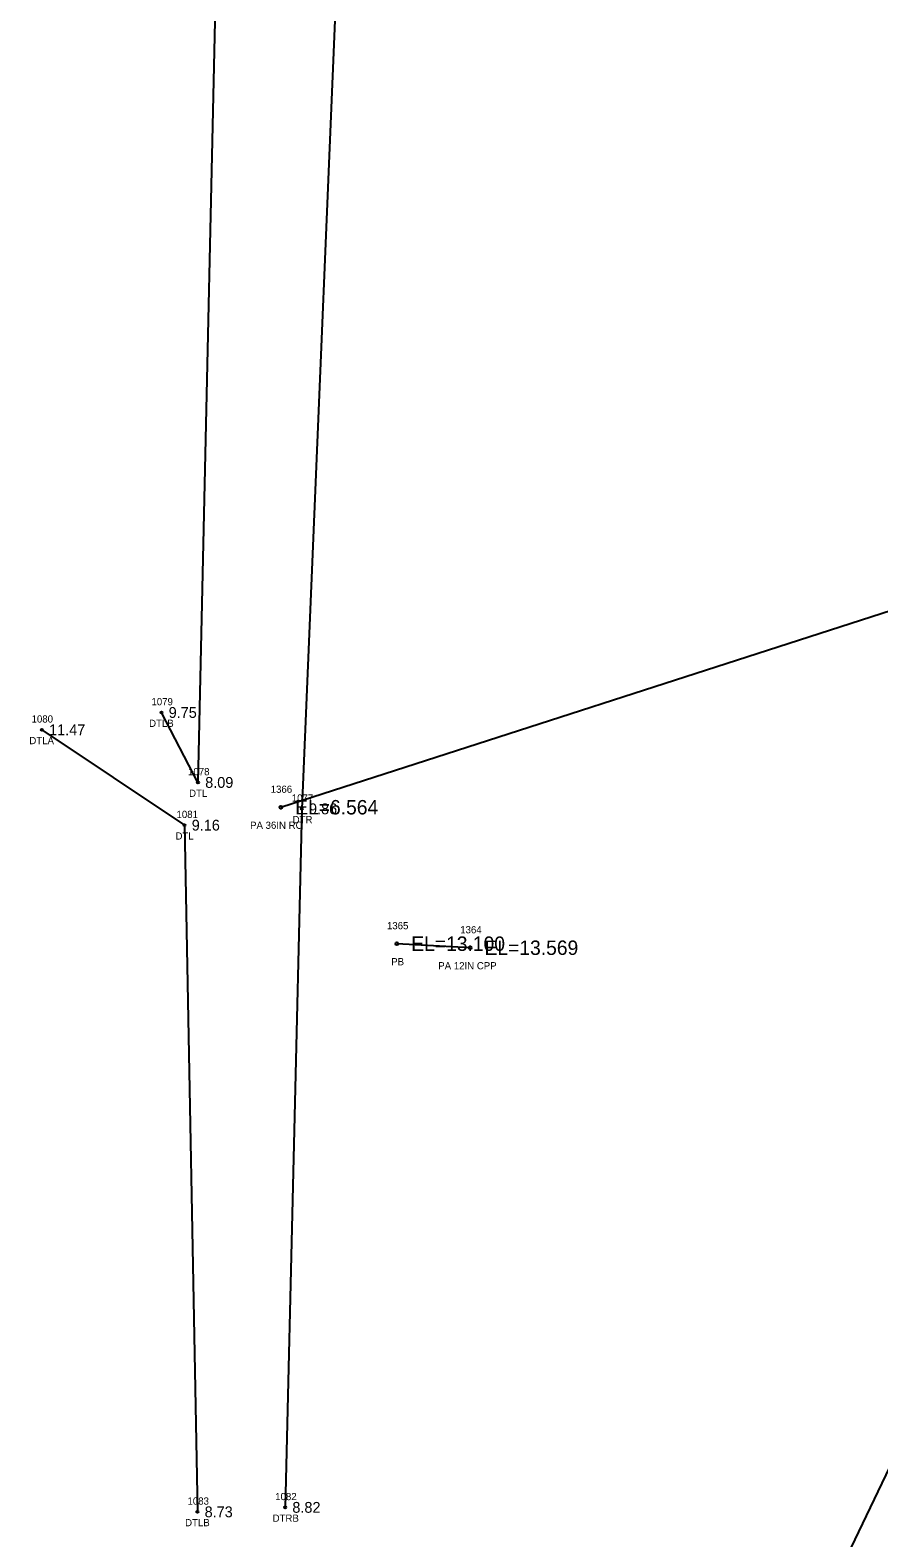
# Model space of a CAD drawing. Extents: x 2072307 to 2072993, y 127574 to 129736.
# Drawn here: x 2072379 to 2072496.8, y 129052.1 to 129261.4 of the extents above; entities that cross this region are included whole.
import ezdxf

# ---------------------------------------------------------------- set-up
doc = ezdxf.new("R2010")
doc.units = 0
for name, color, linetype in [('RD_EX_DR_Pipe', 7, 'Continuous'), ('RD_EX_DR_Pipe_txCode', 7, 'Continuous'), ('RD_EX_H2O', 7, 'Continuous'), ('RD_EX_H2O_txCode', 7, 'Continuous'), ('RD_EX_TX_H2O_ELEV', 7, 'Continuous'), ('RD_SMD_Locator', 7, 'Continuous'), ('RD_TX_Pipe_ElevEX', 7, 'Continuous')]:
    doc.layers.add(name, color=color, linetype=linetype)

msp = doc.modelspace()

# ---------------------------------------------------------------- linework, layer by layer
at = {"layer": 'RD_EX_DR_Pipe'}
for p, q in [((2072413.78, 129153.52), (2072668.09, 129235.65)), ((2072440.06, 129134.02), (2072429.89, 129134.58)), ((2072442.84, 128946.09), (2072506.82, 129079.71))]:
    msp.add_line(p, q, dxfattribs=at)
at = {"layer": 'RD_EX_H2O'}
for points in [[(2072430.99, 129475.23), (2072426.01, 129368.3), (2072422.66, 129295.95), (2072416.7, 129153.3), (2072414.39, 129056.34)], [(2072405.39, 129473.9), (2072401.06, 129369.87), (2072405.35, 129295.82), (2072402.29, 129156.96), (2072397.22, 129166.67)], [(2072380.62, 129164.27), (2072400.42, 129151.03), (2072402.21, 129055.72)]]:
    msp.add_lwpolyline(points, dxfattribs=at)
at = {"layer": 'RD_SMD_Locator'}
for centre, radius in [((2072397.22, 129166.67), 0.15), ((2072380.62, 129164.27), 0.15), ((2072402.29, 129156.96), 0.15), ((2072413.78, 129153.52), 0.2), ((2072416.7, 129153.3), 0.15), ((2072400.42, 129151.03), 0.15), ((2072429.89, 129134.58), 0.2), ((2072440.06, 129134.02), 0.2), ((2072414.39, 129056.34), 0.15), ((2072402.21, 129055.72), 0.15)]:
    msp.add_circle(centre, radius, dxfattribs=at)

# ---------------------------------------------------------------- texts
at = {"layer": 'RD_EX_DR_Pipe_txCode'}
for s, p in [('1366', (2072412.38, 129155.52)), ('PA 36IN RC', (2072409.52, 129150.52)), ('1365', (2072428.52, 129136.58)), ('1364', (2072438.69, 129136.02)), ('PB', (2072429.11, 129131.58)), ('PA 12IN CPP', (2072435.64, 129131.02))]:
    msp.add_text(s, height=1, dxfattribs=at).set_placement(p)
at = {"layer": 'RD_EX_H2O_txCode'}
for s, p in [('1079', (2072395.83, 129167.67)), ('1080', (2072379.19, 129165.27)), ('DTLB', (2072395.5, 129164.67)), ('DTLA', (2072378.88, 129162.27)), ('1078', (2072400.91, 129157.96)), ('DTL', (2072401.05, 129154.96)), ('1077', (2072415.31, 129154.3)), ('1081', (2072399.31, 129152.03)), ('DTR', (2072415.43, 129151.3)), ('DTL', (2072399.17, 129149.03)), ('1082', (2072413.01, 129057.34)), ('1083', (2072400.83, 129056.72)), ('DTLB', (2072400.5, 129053.72)), ('DTRB', (2072412.65, 129054.34))]:
    msp.add_text(s, height=1, dxfattribs=at).set_placement(p)
at = {"layer": 'RD_EX_TX_H2O_ELEV'}
for s, p in [('9.75', (2072398.22, 129165.92)), ('11.47', (2072381.62, 129163.52)), ('8.09', (2072403.29, 129156.21)), ('9.86', (2072417.7, 129152.55)), ('9.16', (2072401.42, 129150.28)), ('8.73', (2072403.21, 129054.97)), ('8.82', (2072415.39, 129055.59))]:
    msp.add_text(s, height=1.5, dxfattribs=at).set_placement(p)
at = {"layer": 'RD_TX_Pipe_ElevEX'}
for s, p in [('EL=6.564', (2072415.78, 129152.52)), ('EL=13.100', (2072431.89, 129133.58)), ('EL=13.569', (2072442.06, 129133.02))]:
    msp.add_text(s, height=2, dxfattribs=at).set_placement(p)

doc.saveas('drawing.dxf')
